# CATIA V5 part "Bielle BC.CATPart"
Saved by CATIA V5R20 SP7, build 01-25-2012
Part number: Bielle BC
Publications: "Point.1", "Point.2", "Droite.2", "Droite.3"
Bounding box of the stored display mesh (mm): x -10 to 10, y 0 to 750, z 0 to 0
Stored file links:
  U:\IAO\IAO\IAO\Bielle BC.CATPart
  U:\IAO\IAO\IAO\Squelette.CATProduct
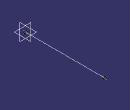
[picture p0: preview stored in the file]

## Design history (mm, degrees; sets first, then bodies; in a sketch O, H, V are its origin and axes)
External parameters (linked from other documents)
  `External.Longueur BC BE` = 750 mm
  `External.Longueur Demi Pivot` = 10 mm
Body1 (main body)
  Point1: (0, 0, 0)
  Line1: type PtDir, RefPoint Point1, Direction zx-plane, Start 0, End 750 {= `External.Longueur BC BE`}
  Point2: (0, 0, 0), relative to vertex of Line1
  Line2: type PtDir, RefPoint Point1, Direction yz-plane, Start -10, End 10 {= `External.Longueur Demi Pivot`}
  Line3: type PtDir, RefPoint Point2, Direction yz-plane, Start -10, End 10 {= `External.Longueur Demi Pivot`}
